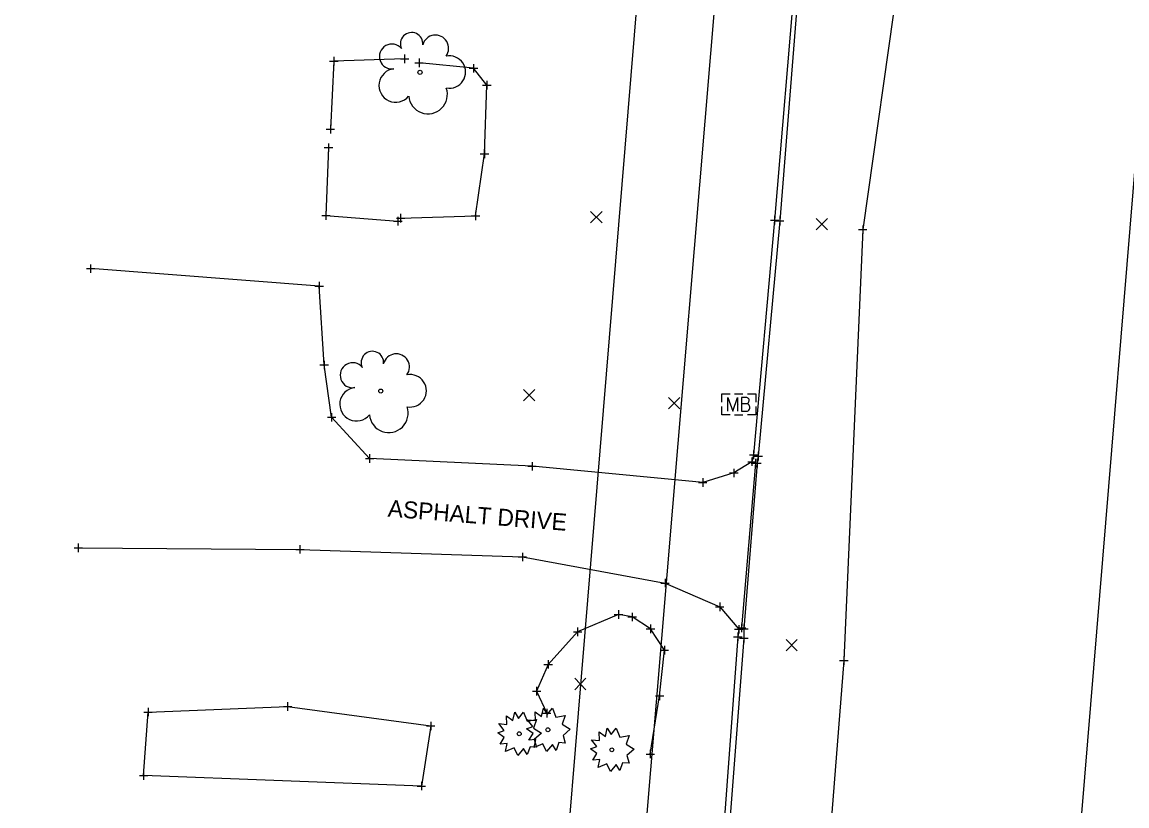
# Model space of a CAD drawing. Extents: x 1380550 to 1381945, y 468927 to 470496.
# Drawn here: x 1381462.2 to 1381592.3, y 469469.7 to 469561.9 of the extents above; entities that cross this region are included whole.
import ezdxf

# ---------------------------------------------------------------- set-up
doc = ezdxf.new("R2010")
doc.units = 0
for name, color, linetype in [('PV_X_COP', 7, 'Continuous'), ('PV_X_Curb', 7, 'Continuous'), ('PV_X_Driveway', 7, 'Continuous'), ('PV_X_EOP', 7, 'Continuous'), ('RD_X_Cells', 7, 'Continuous'), ('RD_X_Fence', 7, 'Continuous'), ('RD_X_Text', 7, 'Continuous'), ('RW_X_Esmt_General', 7, 'Continuous'), ('SV_X_Random_Point', 7, 'Continuous'), ('SV_X_Shot_Marker', 7, 'Continuous'), ('UT_X_Electric', 7, 'Continuous'), ('UT_X_Telecom', 7, 'Continuous'), ('VG_X_Cells', 7, 'Continuous'), ('VG_X_Flower_Bed', 7, 'Continuous'), ('VG_X_Shrub_Line_Lt', 7, 'Continuous')]:
    doc.layers.add(name, color=color, linetype=linetype)

msp = doc.modelspace()

# ---------------------------------------------------------------- linework, layer by layer
at = {"layer": 'PV_X_COP'}
msp.add_lwpolyline([(1381585.99, 469815.58), (1381581.29, 469760.78), (1381580.3, 469747.86), (1381578.72, 469729.45), (1381576.78, 469708.95), (1381575.29, 469689.79), (1381572.76, 469657.56), (1381569.36, 469615.7), (1381565.36, 469567.23), (1381561.16, 469537.52), (1381558.94, 469486.81), (1381555.39, 469442.03), (1381550.97, 469391.02), (1381547.28, 469345.9), (1381541.95, 469289.55), (1381537.19, 469231.27), (1381533.05, 469168.09), (1381530.32, 469133.74), (1381523.97, 469065.08), (1381520.12, 469021.37), (1381518.18, 469001.31)], dxfattribs=at)
at = {"layer": 'PV_X_Curb'}
for points in [[(1381553.19, 469568.93), (1381553.23, 469567.99), (1381550.79, 469538.62), (1381548.32, 469511.01), (1381548.12, 469510.21)], [(1381546.56, 469490.49), (1381546.46, 469489.61), (1381542.99, 469442.93), (1381540.42, 469414.14), (1381540.26, 469413.42)]]:
    msp.add_lwpolyline(points, dxfattribs=at)
at = {"layer": 'PV_X_Driveway'}
for points in [[(1381548.12, 469510.21), (1381545.98, 469508.88), (1381542.32, 469507.76), (1381522.23, 469509.67), (1381503.11, 469510.58), (1381498.63, 469515.43), (1381497.75, 469521.59), (1381497.16, 469530.86), (1381470.26, 469532.93)], [(1381548.12, 469510.21), (1381548.54, 469510.05), (1381546.9, 469490.64), (1381546.56, 469490.49)], [(1381468.81, 469500.07), (1381494.9, 469499.89), (1381521.09, 469499), (1381537.89, 469495.93), (1381544.32, 469493.13), (1381546.56, 469490.49)]]:
    msp.add_lwpolyline(points, dxfattribs=at)
at = {"layer": 'PV_X_EOP'}
msp.add_lwpolyline([(1381553.84, 469569.16), (1381551.39, 469538.56), (1381548.86, 469510.86), (1381548.72, 469510.03), (1381547.16, 469490.53), (1381547.16, 469489.45), (1381543.59, 469442.93), (1381541.04, 469414.11), (1381541, 469413.22), (1381539.53, 469394.02), (1381539.58, 469392.93), (1381538.09, 469374.98)], dxfattribs=at)
at = {"layer": 'RD_X_Cells'}
for p, q in [((1381546.06, 469518.18), (1381547.06, 469518.18)), ((1381546.57, 469516.96), (1381546.57, 469516.96)), ((1381546.06, 469515.74), (1381547.06, 469515.74))]:
    msp.add_line(p, q, dxfattribs=at)
for points in [[(1381544.57, 469517.21), (1381544.57, 469518.18), (1381545.54, 469518.18)], [(1381547.58, 469518.18), (1381548.57, 469518.18), (1381548.57, 469517.21)], [(1381545.54, 469515.74), (1381544.57, 469515.74), (1381544.57, 469516.71)], [(1381545.27, 469516.16), (1381545.27, 469517.76), (1381545.85, 469516.16), (1381546.41, 469517.76), (1381546.41, 469516.16)], [(1381547.59, 469517.03), (1381547.65, 469517.09), (1381547.69, 469517.13), (1381547.72, 469517.17), (1381547.73, 469517.19), (1381547.76, 469517.24), (1381547.77, 469517.28), (1381547.79, 469517.37), (1381547.79, 469517.41), (1381547.79, 469517.46), (1381547.78, 469517.53), (1381547.76, 469517.6), (1381547.72, 469517.65), (1381547.65, 469517.7), (1381547.6, 469517.72), (1381547.58, 469517.73), (1381547.52, 469517.76), (1381546.9, 469517.76), (1381546.9, 469516.16), (1381547.59, 469516.16), (1381547.68, 469516.21), (1381547.76, 469516.27), (1381547.82, 469516.37), (1381547.86, 469516.49), (1381547.87, 469516.6), (1381547.87, 469516.68), (1381547.84, 469516.75), (1381547.79, 469516.86), (1381547.73, 469516.94), (1381547.59, 469517.03), (1381546.9, 469517.03)], [(1381548.57, 469516.71), (1381548.57, 469515.74), (1381547.58, 469515.74)]]:
    msp.add_lwpolyline(points, dxfattribs=at)
at = {"layer": 'RD_X_Fence'}
for points in [[(1381507.23, 469557.62), (1381498.89, 469557.34), (1381498.49, 469549.33)], [(1381498.26, 469547.17), (1381497.97, 469539.17), (1381506.42, 469538.51)]]:
    msp.add_lwpolyline(points, dxfattribs=at)
at = {"layer": 'RW_X_Esmt_General'}
for points in [[(1381490.4, 469029.46), (1381590.2, 470237.18), (1380558.69, 470277.03)], [(1381783.19, 470213.89), (1381648.78, 470217.49), (1381563.79, 469189.03)]]:
    msp.add_lwpolyline(points, dxfattribs=at)
at = {"layer": 'SV_X_Random_Point'}
for p, q in [((1381529.13, 469538.3), (1381530.47, 469539.63)), ((1381529.13, 469539.63), (1381530.47, 469538.3)), ((1381555.69, 469537.49), (1381557.02, 469538.83)), ((1381555.69, 469538.83), (1381557.02, 469537.49)), ((1381521.21, 469517.37), (1381522.54, 469518.71)), ((1381521.21, 469518.71), (1381522.54, 469517.37)), ((1381538.3, 469516.42), (1381539.63, 469517.76)), ((1381538.3, 469517.76), (1381539.63, 469516.42)), ((1381552.13, 469487.96), (1381553.46, 469489.3)), ((1381552.13, 469489.3), (1381553.46, 469487.96)), ((1381527.25, 469483.38), (1381528.58, 469484.72)), ((1381527.25, 469484.72), (1381528.58, 469483.38))]:
    msp.add_line(p, q, dxfattribs=at)
at = {"layer": 'SV_X_Shot_Marker'}
for p, q in [((1381498.39, 469557.34), (1381499.39, 469557.34)), ((1381498.89, 469557.84), (1381498.89, 469556.84)), ((1381498.89, 469557.34), (1381498.89, 469557.34)), ((1381506.73, 469557.62), (1381507.73, 469557.62)), ((1381507.23, 469558.12), (1381507.23, 469557.12)), ((1381507.23, 469557.62), (1381507.23, 469557.62)), ((1381508.42, 469557.14), (1381509.42, 469557.14)), ((1381508.92, 469557.64), (1381508.92, 469556.64)), ((1381508.92, 469557.14), (1381508.92, 469557.14)), ((1381515.34, 469557), (1381515.34, 469556)), ((1381514.84, 469556.5), (1381515.84, 469556.5)), ((1381515.34, 469556.5), (1381515.34, 469556.5)), ((1381516.4, 469554.53), (1381517.4, 469554.53)), ((1381516.9, 469555.03), (1381516.9, 469554.03)), ((1381516.9, 469554.53), (1381516.9, 469554.53)), ((1381497.99, 469549.33), (1381498.99, 469549.33)), ((1381498.49, 469549.83), (1381498.49, 469548.83)), ((1381498.49, 469549.33), (1381498.49, 469549.33)), ((1381497.76, 469547.17), (1381498.76, 469547.17)), ((1381498.26, 469547.67), (1381498.26, 469546.67)), ((1381498.26, 469547.17), (1381498.26, 469547.17)), ((1381516.63, 469546.93), (1381516.63, 469545.93)), ((1381516.13, 469546.43), (1381517.13, 469546.43)), ((1381516.63, 469546.43), (1381516.63, 469546.43)), ((1381497.47, 469539.17), (1381498.47, 469539.17)), ((1381497.97, 469539.67), (1381497.97, 469538.67)), ((1381497.97, 469539.17), (1381497.97, 469539.17)), ((1381506.26, 469538.86), (1381507.26, 469538.86)), ((1381506.42, 469539.01), (1381506.42, 469538.01)), ((1381506.76, 469539.36), (1381506.76, 469538.36)), ((1381506.76, 469538.86), (1381506.76, 469538.86)), ((1381515.08, 469539.12), (1381516.08, 469539.12)), ((1381515.58, 469539.62), (1381515.58, 469538.62)), ((1381515.58, 469539.12), (1381515.58, 469539.12)), ((1381550.79, 469539.12), (1381550.79, 469538.12)), ((1381551.39, 469539.06), (1381551.39, 469538.06)), ((1381505.92, 469538.51), (1381506.92, 469538.51)), ((1381506.42, 469538.51), (1381506.42, 469538.51)), ((1381550.29, 469538.62), (1381551.29, 469538.62)), ((1381550.79, 469538.62), (1381550.79, 469538.62)), ((1381550.89, 469538.56), (1381551.89, 469538.56)), ((1381551.39, 469538.56), (1381551.39, 469538.56)), ((1381560.66, 469537.52), (1381561.66, 469537.52)), ((1381561.16, 469538.02), (1381561.16, 469537.02)), ((1381561.16, 469537.52), (1381561.16, 469537.52)), ((1381469.76, 469532.93), (1381470.76, 469532.93)), ((1381470.26, 469533.43), (1381470.26, 469532.43)), ((1381470.26, 469532.93), (1381470.26, 469532.93)), ((1381497.16, 469531.36), (1381497.16, 469530.36)), ((1381496.66, 469530.86), (1381497.66, 469530.86)), ((1381497.16, 469530.86), (1381497.16, 469530.86)), ((1381497.75, 469522.09), (1381497.75, 469521.09)), ((1381497.25, 469521.59), (1381498.25, 469521.59)), ((1381497.75, 469521.59), (1381497.75, 469521.59)), ((1381498.13, 469515.43), (1381499.13, 469515.43)), ((1381498.63, 469515.93), (1381498.63, 469514.93)), ((1381498.63, 469515.43), (1381498.63, 469515.43)), ((1381548.32, 469511.51), (1381548.32, 469510.51)), ((1381502.61, 469510.58), (1381503.61, 469510.58)), ((1381503.11, 469511.08), (1381503.11, 469510.08)), ((1381503.11, 469510.58), (1381503.11, 469510.58)), ((1381522.23, 469510.17), (1381522.23, 469509.17)), ((1381547.62, 469510.21), (1381548.62, 469510.21)), ((1381547.62, 469510.21), (1381548.62, 469510.21)), ((1381547.62, 469510.21), (1381548.62, 469510.21)), ((1381547.82, 469511.01), (1381548.82, 469511.01)), ((1381548.12, 469510.71), (1381548.12, 469509.71)), ((1381548.12, 469510.71), (1381548.12, 469509.71)), ((1381548.12, 469510.71), (1381548.12, 469509.71)), ((1381548.12, 469510.21), (1381548.12, 469510.21)), ((1381548.12, 469510.21), (1381548.12, 469510.21)), ((1381548.12, 469510.21), (1381548.12, 469510.21)), ((1381548.32, 469511.01), (1381548.32, 469511.01)), ((1381548.36, 469510.86), (1381549.36, 469510.86)), ((1381548.54, 469510.55), (1381548.54, 469509.55)), ((1381548.72, 469510.53), (1381548.72, 469509.53)), ((1381548.86, 469511.36), (1381548.86, 469510.36)), ((1381548.86, 469510.86), (1381548.86, 469510.86)), ((1381521.73, 469509.67), (1381522.73, 469509.67)), ((1381522.23, 469509.67), (1381522.23, 469509.67)), ((1381545.48, 469508.88), (1381546.48, 469508.88)), ((1381545.98, 469509.38), (1381545.98, 469508.38)), ((1381545.98, 469508.88), (1381545.98, 469508.88)), ((1381548.04, 469510.05), (1381549.04, 469510.05)), ((1381548.22, 469510.03), (1381549.22, 469510.03)), ((1381548.54, 469510.05), (1381548.54, 469510.05)), ((1381548.72, 469510.03), (1381548.72, 469510.03)), ((1381541.82, 469507.76), (1381542.82, 469507.76)), ((1381542.32, 469508.26), (1381542.32, 469507.26)), ((1381542.32, 469507.76), (1381542.32, 469507.76)), ((1381468.31, 469500.07), (1381469.31, 469500.07)), ((1381468.81, 469500.57), (1381468.81, 469499.57)), ((1381468.81, 469500.07), (1381468.81, 469500.07)), ((1381494.4, 469499.89), (1381495.4, 469499.89)), ((1381494.9, 469500.39), (1381494.9, 469499.39)), ((1381494.9, 469499.89), (1381494.9, 469499.89)), ((1381520.59, 469499), (1381521.59, 469499)), ((1381521.09, 469499.5), (1381521.09, 469498.5)), ((1381521.09, 469499), (1381521.09, 469499)), ((1381537.39, 469495.93), (1381538.39, 469495.93)), ((1381537.89, 469496.43), (1381537.89, 469495.43)), ((1381537.89, 469495.93), (1381537.89, 469495.93)), ((1381544.32, 469493.63), (1381544.32, 469492.63)), ((1381531.91, 469492.23), (1381532.91, 469492.23)), ((1381532.41, 469492.73), (1381532.41, 469491.73)), ((1381532.41, 469492.23), (1381532.41, 469492.23)), ((1381533.52, 469491.94), (1381534.52, 469491.94)), ((1381534.02, 469492.44), (1381534.02, 469491.44)), ((1381534.02, 469491.94), (1381534.02, 469491.94)), ((1381543.82, 469493.13), (1381544.82, 469493.13)), ((1381544.32, 469493.13), (1381544.32, 469493.13)), ((1381527.6, 469490.69), (1381527.6, 469489.69)), ((1381536.18, 469491.04), (1381536.18, 469490.04)), ((1381546.4, 469490.64), (1381547.4, 469490.64)), ((1381546.56, 469490.99), (1381546.56, 469489.99)), ((1381546.56, 469490.99), (1381546.56, 469489.99)), ((1381546.56, 469490.99), (1381546.56, 469489.99)), ((1381546.9, 469491.14), (1381546.9, 469490.14)), ((1381546.9, 469490.64), (1381546.9, 469490.64)), ((1381547.16, 469491.03), (1381547.16, 469490.03)), ((1381527.1, 469490.19), (1381528.1, 469490.19)), ((1381527.6, 469490.19), (1381527.6, 469490.19)), ((1381535.68, 469490.54), (1381536.68, 469490.54)), ((1381536.18, 469490.54), (1381536.18, 469490.54)), ((1381545.96, 469489.61), (1381546.96, 469489.61)), ((1381546.06, 469490.49), (1381547.06, 469490.49)), ((1381546.06, 469490.49), (1381547.06, 469490.49)), ((1381546.06, 469490.49), (1381547.06, 469490.49)), ((1381546.46, 469490.11), (1381546.46, 469489.11)), ((1381546.46, 469489.61), (1381546.46, 469489.61)), ((1381546.56, 469490.49), (1381546.56, 469490.49)), ((1381546.56, 469490.49), (1381546.56, 469490.49)), ((1381546.56, 469490.49), (1381546.56, 469490.49)), ((1381546.66, 469490.53), (1381547.66, 469490.53)), ((1381546.66, 469489.45), (1381547.66, 469489.45)), ((1381547.16, 469490.53), (1381547.16, 469490.53)), ((1381547.16, 469489.95), (1381547.16, 469488.95)), ((1381547.16, 469489.45), (1381547.16, 469489.45)), ((1381537.81, 469488.52), (1381537.81, 469487.52)), ((1381524.12, 469486.86), (1381524.12, 469485.86)), ((1381537.31, 469488.02), (1381538.31, 469488.02)), ((1381537.81, 469488.02), (1381537.81, 469488.02)), ((1381558.44, 469486.81), (1381559.44, 469486.81)), ((1381558.94, 469487.31), (1381558.94, 469486.31)), ((1381558.94, 469486.81), (1381558.94, 469486.81)), ((1381523.62, 469486.36), (1381524.62, 469486.36)), ((1381524.12, 469486.36), (1381524.12, 469486.36)), ((1381522.27, 469483.2), (1381523.27, 469483.2)), ((1381522.77, 469483.7), (1381522.77, 469482.7)), ((1381522.77, 469483.2), (1381522.77, 469483.2)), ((1381537.25, 469483.15), (1381537.25, 469482.15)), ((1381493.45, 469481.89), (1381493.45, 469480.89)), ((1381536.75, 469482.65), (1381537.75, 469482.65)), ((1381537.25, 469482.65), (1381537.25, 469482.65)), ((1381476.52, 469480.75), (1381477.52, 469480.75)), ((1381477.02, 469481.25), (1381477.02, 469480.25)), ((1381477.02, 469480.75), (1381477.02, 469480.75)), ((1381492.95, 469481.39), (1381493.95, 469481.39)), ((1381493.45, 469481.39), (1381493.45, 469481.39)), ((1381523.46, 469480.62), (1381524.46, 469480.62)), ((1381523.96, 469481.12), (1381523.96, 469480.12)), ((1381523.96, 469480.62), (1381523.96, 469480.62)), ((1381509.8, 469479.11), (1381510.8, 469479.11)), ((1381510.3, 469479.61), (1381510.3, 469478.61)), ((1381510.3, 469479.11), (1381510.3, 469479.11)), ((1381535.65, 469475.8), (1381536.65, 469475.8)), ((1381536.15, 469476.3), (1381536.15, 469475.3)), ((1381536.15, 469475.8), (1381536.15, 469475.8)), ((1381476.5, 469473.77), (1381476.5, 469472.77)), ((1381476, 469473.27), (1381477, 469473.27)), ((1381476.5, 469473.27), (1381476.5, 469473.27)), ((1381509.2, 469472.54), (1381509.2, 469471.54)), ((1381508.7, 469472.04), (1381509.7, 469472.04)), ((1381509.2, 469472.04), (1381509.2, 469472.04))]:
    msp.add_line(p, q, dxfattribs=at)
at = {"layer": 'UT_X_Electric'}
msp.add_lwpolyline([(1381665.56, 470247.4), (1381595.79, 470220.83), (1381581.26, 470018.2), (1381571.97, 469887.64), (1381559.77, 469757.41), (1381543.86, 469565.78), (1381529.17, 469390.12), (1381515.28, 469203.1), (1381540.8, 469054.26)], dxfattribs=at)
at = {"layer": 'UT_X_Telecom'}
msp.add_lwpolyline([(1381665.56, 470247.4), (1381595.35, 470217.51), (1381581.26, 470018.2), (1381571.97, 469887.64), (1381559.77, 469757.41), (1381543.86, 469565.78), (1381529.17, 469390.12), (1381515.28, 469203.1), (1381540.8, 469054.26)], dxfattribs=at)
at = {"layer": 'VG_X_Cells'}
for points in [[(1381520.63, 469480), (1381521.24, 469480.73), (1381521.65, 469479.68), (1381522.74, 469479.86), (1381522.41, 469478.85), (1381523.35, 469478.25), (1381522.49, 469477.52), (1381522.74, 469476.61), (1381521.99, 469476.67), (1381521.67, 469475.76), (1381521.24, 469476.45), (1381520.56, 469475.64), (1381520.13, 469476.52), (1381519.11, 469476.09), (1381519.3, 469477.03), (1381518.49, 469476.95), (1381518.96, 469477.74), (1381518.2, 469478.31), (1381518.93, 469478.57), (1381518.33, 469479.38), (1381519.26, 469479.27), (1381519.23, 469480.3), (1381519.98, 469479.74), (1381520.19, 469480.72), (1381520.63, 469480)], [(1381524.01, 469480.47), (1381524.62, 469481.21), (1381525.03, 469480.15), (1381526.13, 469480.33), (1381525.79, 469479.32), (1381526.73, 469478.73), (1381525.88, 469477.99), (1381526.13, 469477.08), (1381525.37, 469477.15), (1381525.05, 469476.23), (1381524.62, 469476.93), (1381523.94, 469476.11), (1381523.51, 469477), (1381522.49, 469476.57), (1381522.69, 469477.51), (1381521.87, 469477.42), (1381522.35, 469478.21), (1381521.58, 469478.78), (1381522.32, 469479.05), (1381521.71, 469479.85), (1381522.64, 469479.74), (1381522.61, 469480.78), (1381523.36, 469480.21), (1381523.57, 469481.19), (1381524.01, 469480.47)], [(1381531.54, 469478.11), (1381532.14, 469478.85), (1381532.56, 469477.8), (1381533.65, 469477.98), (1381533.31, 469476.96), (1381534.25, 469476.37), (1381533.4, 469475.63), (1381533.65, 469474.72), (1381532.89, 469474.79), (1381532.57, 469473.88), (1381532.14, 469474.57), (1381531.46, 469473.75), (1381531.03, 469474.64), (1381530.01, 469474.21), (1381530.21, 469475.15), (1381529.39, 469475.07), (1381529.87, 469475.86), (1381529.1, 469476.42), (1381529.84, 469476.69), (1381529.23, 469477.49), (1381530.16, 469477.38), (1381530.13, 469478.42), (1381530.89, 469477.85), (1381531.09, 469478.84), (1381531.54, 469478.11)]]:
    msp.add_lwpolyline(points, dxfattribs=at)
for centre, radius in [((1381509.04, 469556.03), 0.24), ((1381504.42, 469518.52), 0.24), ((1381520.72, 469478.19), 0.23), ((1381524.1, 469478.66), 0.23), ((1381531.62, 469476.3), 0.23)]:
    msp.add_circle(centre, radius, dxfattribs=at)
for centre, radius, start, end in [((1381508.05, 469559.39), 1.32, 354.0047, 205.9741), ((1381510.86, 469558.86), 1.55, 323.83, 165.0376), ((1381505.73, 469557.89), 1.47, 39.0625, 279.5412), ((1381512.5, 469556.06), 1.91, 259.1453, 101.4596), ((1381506.18, 469554.48), 1.97, 96.1722, 320.5737), ((1381509.98, 469553.42), 2.28, 184.9476, 19.4572), ((1381503.43, 469521.88), 1.32, 354.0047, 205.9741), ((1381501.11, 469520.38), 1.47, 39.0625, 279.5412), ((1381506.24, 469521.35), 1.55, 323.83, 165.0376), ((1381507.88, 469518.55), 1.91, 259.1453, 101.4596), ((1381501.56, 469516.97), 1.97, 96.1722, 320.5737), ((1381505.36, 469515.91), 2.28, 184.9476, 19.4572)]:
    msp.add_arc(centre, radius, start, end, dxfattribs=at)
at = {"layer": 'VG_X_Flower_Bed'}
for points in [[(1381506.76, 469538.86), (1381515.58, 469539.12), (1381516.63, 469546.43), (1381516.9, 469554.53), (1381515.34, 469556.5), (1381508.92, 469557.14)], [(1381536.15, 469475.8), (1381537.25, 469482.65), (1381537.81, 469488.02), (1381536.18, 469490.54), (1381534.02, 469491.94), (1381532.41, 469492.23), (1381527.6, 469490.19), (1381524.12, 469486.36), (1381522.77, 469483.2), (1381523.96, 469480.62)]]:
    msp.add_lwpolyline(points, dxfattribs=at)
at = {"layer": 'VG_X_Shrub_Line_Lt'}
msp.add_lwpolyline([(1381476.5, 469473.27), (1381477.02, 469480.75), (1381493.45, 469481.39), (1381510.3, 469479.11), (1381509.2, 469472.04)], close=True, dxfattribs=at)

# ---------------------------------------------------------------- texts
at = {"layer": 'RD_X_Text'}
msp.add_text('ASPHALT DRIVE', height=2, rotation=355.4428, dxfattribs=at).set_placement((1381505.2, 469503.75))

doc.saveas('drawing.dxf')
